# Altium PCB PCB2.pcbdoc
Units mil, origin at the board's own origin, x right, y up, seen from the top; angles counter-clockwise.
Board outline 7800 x 6000 mil, 2 copper layers (Top Layer, Bottom Layer); 55 components, 47 nets, 199 pads, 12 vias.
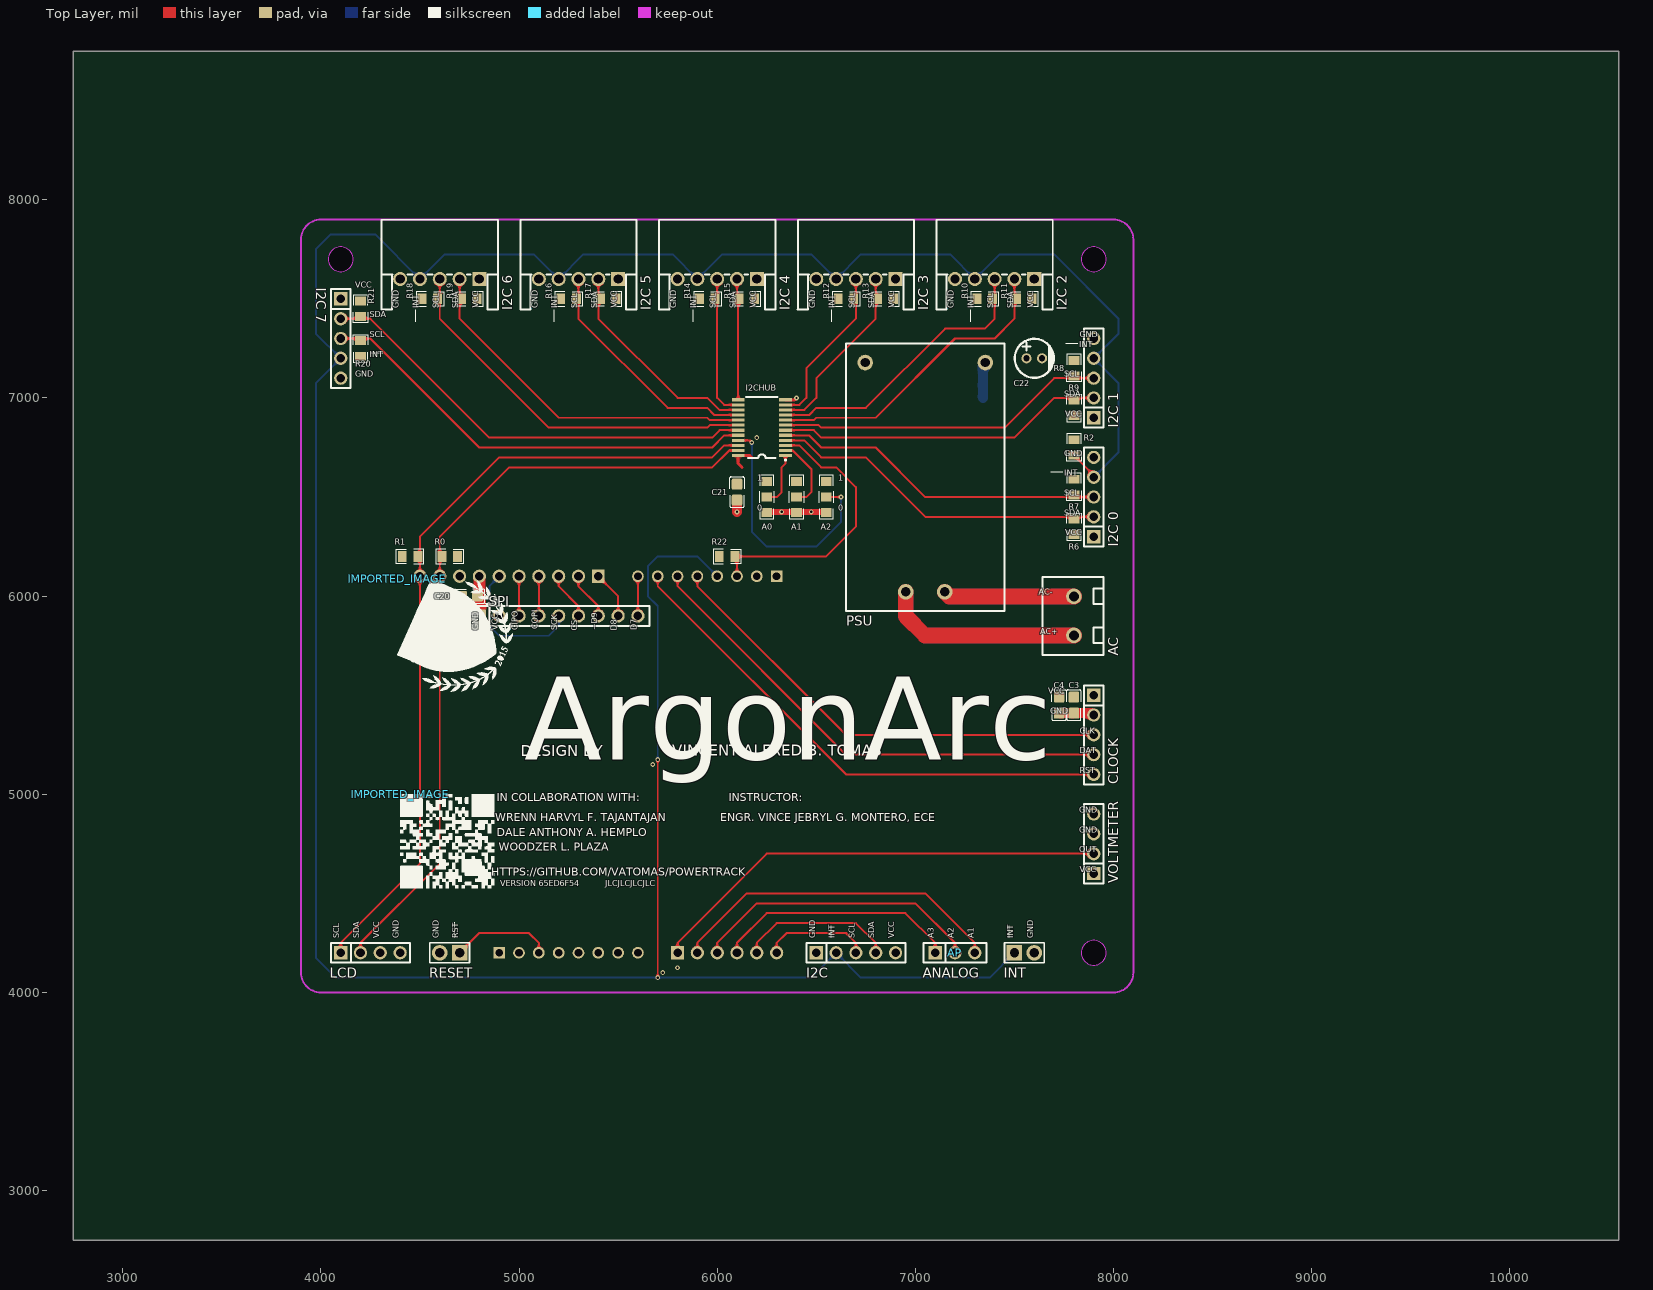
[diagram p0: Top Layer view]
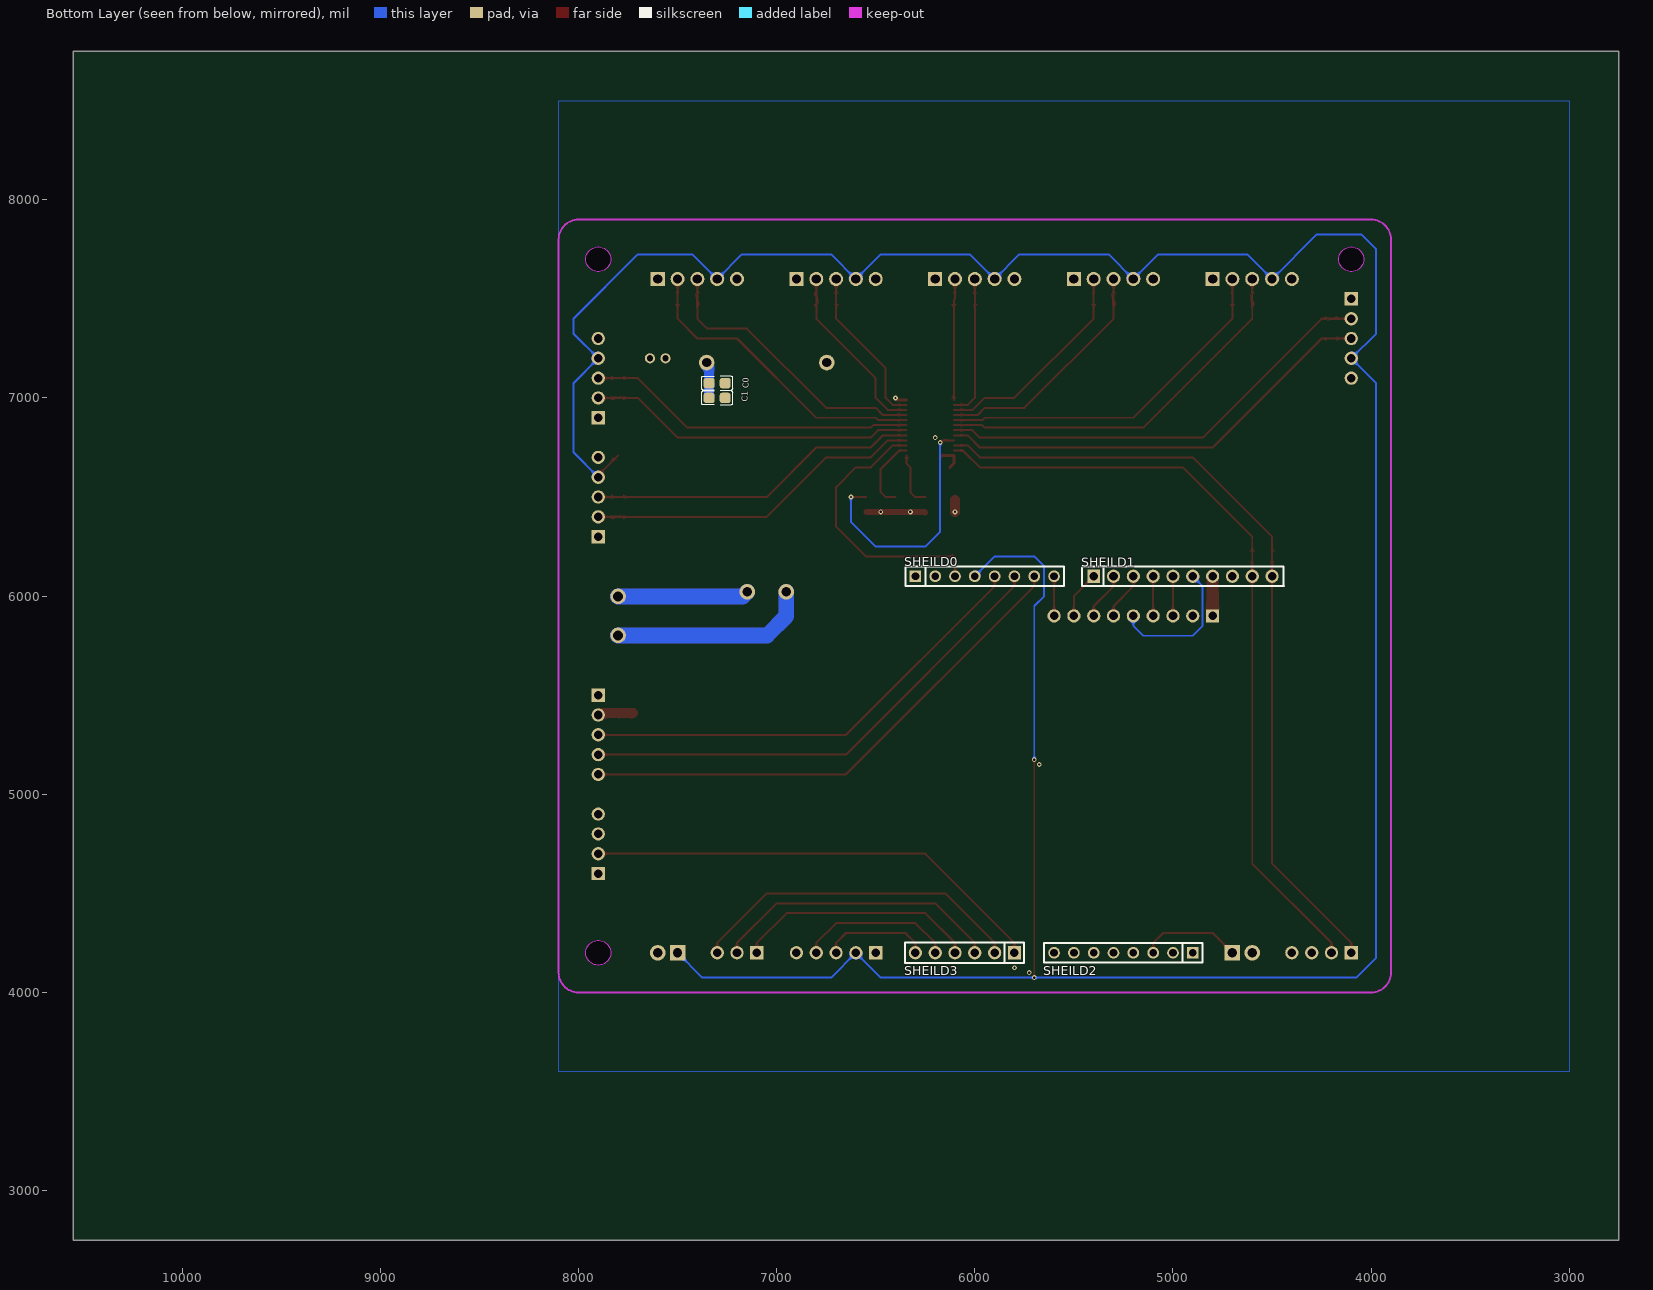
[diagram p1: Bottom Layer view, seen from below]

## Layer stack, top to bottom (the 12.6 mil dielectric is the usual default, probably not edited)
Top Layer: signal copper (thickness not stored)
Dielectric: dielectric 12.6, FR-4, Dk 4.8
Bottom Layer: signal copper (thickness not stored)

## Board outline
10550,2750 2750,2750 2750,8750 10550,8750
cut-out: 7962.99,4200 ccw(c7900,4199.64) 7837.01,4200 ccw(c7900,4200.36)
cut-out: 4162.99,7700 ccw(c4100,7699.64) 4037.01,7700 ccw(c4100,7700.36)
cut-out: 7962.99,7700 ccw(c7900,7699.64) 7837.01,7700 ccw(c7900,7700.36)

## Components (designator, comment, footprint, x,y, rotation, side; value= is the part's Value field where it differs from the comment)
A0 "Solder Switch" "Solder Switch" 6250,6500 r270 top
A1 "Solder Switch" "Solder Switch" 6400,6500 r270 top
A2 "Solder Switch" "Solder Switch" 6550,6500 r270 top
AC "WJ126V-5.0-2P" CONN-TH_WJ126V-5.0-2P 7800,5900 r180 top
AP "PZ254V-11-03P" HDR-TH_3P-P2.54-V-M 7200,4200 r0 top
C0 "CL21B104KBCNNNC" C0805#1 7300,7075 r180 bottom
C1 "CL21B105KBFNNNE" C0805#1 7300,7000 r180 bottom
C3 "CL21B104KBCNNNC" C0805#2 7800,5450 r270 top
C4 "CL21B105KBFNNNE" C0805#2 7725,5450 r270 top
C20 "CL21B104KBCNNNC" C0805#2 4750,6000 r0 top
C21 "CL21B104KBCNNNC" C0805#2 6100,6525 r270 top
C22 "KS476M025D07RR0VH2FP0" CAP-TH_BD5.0-P2.00-D0.8-FD 7600,7200 r0 top
CLOCK "PZ254V-11-05P" HDR-TH_5P-P2.54-V-M 7900,5300 r270 top
I2C "PZ254V-11-05P" HDR-TH_5P-P2.54-V-M 6700,4200 r0 top
"I2C 0" "PZ254V-11-05P" HDR-TH_5P-P2.54-V-M 7900,6500 r90 top
"I2C 1" "PZ254V-11-05P" HDR-TH_5P-P2.54-V-M 7900,7100 r90 top
"I2C 2" "S5B-XH-A-1(LF)(SN)" CONN-TH_S5B-XH-A-1-LF-SN 7400,7600 r0 top
"I2C 3" "S5B-XH-A-1(LF)(SN)" CONN-TH_S5B-XH-A-1-LF-SN 6700,7600 r0 top
"I2C 4" "S5B-XH-A-1(LF)(SN)" CONN-TH_S5B-XH-A-1-LF-SN 6000,7600 r0 top
"I2C 5" "S5B-XH-A-1(LF)(SN)" CONN-TH_S5B-XH-A-1-LF-SN 5300,7600 r0 top
"I2C 6" "S5B-XH-A-1(LF)(SN)" CONN-TH_S5B-XH-A-1-LF-SN 4600,7600 r0 top
"I2C 7" "PZ254V-11-05P" HDR-TH_5P-P2.54-V-M 4100,7300 r270 top
I2CHUB "TCA9548APWR" TSSOP-24_L7.8-W4.4-P0.65-LS6.4-BL 6225,6850 r90 top
IMPORTED_IMAGE "IMPORTED_IMAGE" IMPORTED_IMAGE 4400,5000 r0 top
IMPORTED_IMAGE "IMPORTED_IMAGE" IMPORTED_IMAGE 4385.55,6087.06 r0 top
INT "PZ254V-11-02P" HDR-TH_2P-P2.54-V-M 7550,4200 r0 top
LCD "PZ254V-11-04P" HDR-TH_4P-P2.54-V-M 4250,4200 r0 top
PSU "HLK-PM01" PWRM-TH_HLK-PM01 7050,6600 r90 top
R0 "0805W8F4701T5E" R0805 4650,6200 r180 top
R1 "0805W8F4701T5E" R0805 4450,6200 r0 top
R2 "0805W8F1002T5E" R0805 7800,6750 r90 top
R6 "0805W8F4701T5E" R0805 7800,6350 r270 top
R7 "0805W8F4701T5E" R0805 7800,6550 r90 top
R8 "0805W8F4701T5E" R0805 7800,7150 r90 top
R9 "0805W8F4701T5E" R0805 7800,6950 r270 top
R10 "0805W8F4701T5E" R0805 7350,7500 r180 top
R11 "0805W8F4701T5E" R0805 7550,7500 r0 top
R12 "0805W8F4701T5E" R0805 6650,7500 r180 top
R13 "0805W8F4701T5E" R0805 6850,7500 r0 top
R14 "0805W8F4701T5E" R0805 5950,7500 r180 top
R15 "0805W8F4701T5E" R0805 6150,7500 r0 top
R16 "0805W8F4701T5E" R0805 5250,7500 r180 top
R17 "0805W8F4701T5E" R0805 5450,7500 r0 top
R18 "0805W8F4701T5E" R0805 4550,7500 r180 top
R19 "0805W8F4701T5E" R0805 4750,7500 r0 top
R20 "0805W8F4701T5E" R0805 4200,7250 r270 top
R21 "0805W8F4701T5E" R0805 4200,7450 r90 top
R22 "0805W8F1002T5E" R0805 6050,6200 r180 top
RESET "PZ254V-11-02P" HDR-TH_2P-P2.54-V-M 4650,4200 r180 top
SHEILD0 "PZ254V-11-08P" HDR-TH_8P-P2.54-V-M 5950,6100 r180 bottom
SHEILD1 "X6511WV-10H-C60D30" HDR-TH_10P-P2.54-V-M 4950,6100 r180 bottom
SHEILD2 "PZ254V-11-08P" HDR-TH_8P-P2.54-V-M 5250,4200 r0 bottom
SHEILD3 "PZ254V-11-06P" HDR-TH_6P-P2.54-V-M 6050,4200 r0 bottom
SPI "PZ254-1-09-Z-8.5" HDR-TH_9P-P2.54-V-M 5200,5900 r0 top
VOLTMETER "PZ254V-11-04P" HDR-TH_4P-P2.54-V-M 7900,4750 r90 top

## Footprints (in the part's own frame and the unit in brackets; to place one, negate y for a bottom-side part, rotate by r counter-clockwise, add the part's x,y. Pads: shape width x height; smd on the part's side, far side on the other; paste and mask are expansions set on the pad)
C0805#1 [mm]
  rrect50% 1.41x1.35 smd: 1(-1.03,0) 2(1.03,0)
  silkscreen extent -1.96,-0.9 1.96,0.9
C0805#2 [mm]
  rrect25% 1.41x1.35 smd: 1(-1.03,0) 2(1.03,0)
  silkscreen extent -1.96,-0.9 1.96,0.9
CAP-TH_BD5.0-P2.00-D0.8-FD [mm]
  round 1.3 hole 0.8: 1(-1,0) 2(1,0)
  silkscreen extent -2.5,-2.5 2.5,2.5
CONN-TH_S5B-XH-A-1-LF-SN [mm]
  rect 1.8x1.8 hole 1.2: 1(5.08,0)
  round 1.8 hole 1.2: 2(2.54,0) 3(0,0) 4(-2.54,0) 5(-5.08,0)
  silkscreen extent -7.46,-3.9 7.45,7.6
CONN-TH_WJ126V-5.0-2P [mm]
  round 2 hole 1.3: 1(0,2.501) 2(0,-2.501)
  silkscreen extent -3.8,-5 4,5
HDR-TH_2P-P2.54-V-M [mm]
  rect 2x2 hole 1.2: 1(-1.27,0)
  round 2 hole 1.2: 2(1.27,0)
  silkscreen extent -2.54,-1.27 2.54,1.27
HDR-TH_3P-P2.54-V-M [mm]
  rect 1.7x1.7 hole 1.1: 1(-2.54,0)
  round 1.7 hole 1.1: 2(0,0) 3(2.54,0)
  silkscreen extent -4.02,-1.27 4.02,1.27
HDR-TH_4P-P2.54-V-M [mm]
  rect 1.7x1.7 hole 1.1: 1(-3.81,0)
  round 1.7 hole 1.1: 2(-1.27,0) 3(1.27,0) 4(3.81,0)
  silkscreen extent -5.08,-1.27 5.08,1.27
HDR-TH_5P-P2.54-V-M [mm]
  rect 1.7x1.7 hole 1.1: 1(-5.08,0)
  round 1.7 hole 1.1: 2(-2.54,0) 3(0,0) 4(2.54,0) 5(5.08,0)
  silkscreen extent -6.35,-1.27 6.35,1.27
HDR-TH_6P-P2.54-V-M [mm]
  rect 1.7x1.7 hole 1.1: 1(-6.35,0)
  round 1.7 hole 1.1: 2(-3.81,0) 3(-1.27,0) 4(1.27,0) 5(3.81,0) 6(6.35,0)
  silkscreen extent -7.6,-1.3 7.65,1.3
HDR-TH_8P-P2.54-V-M [mm]
  rect 1.5x1.5 hole 1: 1(-8.89,0)
  round 1.5 hole 1: 2(-6.35,0) 3(-3.81,0) 4(-1.27,0) 5(1.27,0) 6(3.81,0) 7(6.35,0) 8(8.89,0)
  silkscreen extent -10.16,-1.27 10.16,1.27
HDR-TH_9P-P2.54-V-M [mm]
  rect 1.7x1.7 hole 1.1: 1(-10.16,0)
  round 1.7 hole 1.1: 2(-7.62,0) 3(-5.08,0) 4(-2.54,0) 5(0,0) 6(2.54,0) 7(5.08,0) 8(7.62,0) 9(10.16,0)
  silkscreen extent -11.64,-1.27 11.64,1.27
HDR-TH_10P-P2.54-V-M [mm]
  rect 1.575x1.7 hole 1.1: 1(-11.43,0)
  round 1.7 hole 1.1: 2(-8.89,0) 3(-6.35,0) 4(-3.81,0) 5(-1.27,0) 6(1.27,0) 7(3.81,0) 8(6.35,0) 9(8.89,0) 10(11.43,0)
  silkscreen extent -12.9,-1.27 12.95,1.27
IMPORTED_IMAGE [mil]
  silkscreen extent 0,-475 475,0
PWRM-TH_HLK-PM01 [mm]
  round 2 hole 1.2: 1(-14.7,2.5) 2(-14.7,-2.5) 3(14.7,7.7) 4(14.7,-7.7)
  silkscreen extent -17.14,-10.16 17.14,10.16
R0805 [mm]
  rect 1.133x1.377 smd: 1(-1,0) 2(1,0)
  silkscreen extent -1.76,-0.92 1.76,0.92
"Solder Switch" [mm]
  rect 1.133x1.377 smd: 1(-2,0) 2(0,0) 3(2,0)
  silkscreen extent -2.76,-0.92 2.76,0.92
TSSOP-24_L7.8-W4.4-P0.65-LS6.4-BL [mm]
  rect 0.4x1.65 smd: 1(-3.575,-3.023) 2(-2.925,-3.023) 3(-2.275,-3.023) 4(-1.625,-3.023) 5(-0.975,-3.023) 6(-0.325,-3.023) 7(0.325,-3.023) 8(0.975,-3.023) 9(1.625,-3.023) 10(2.275,-3.023) 11(2.925,-3.023) 12(3.575,-3.023) 13(3.575,3.023) 14(2.925,3.023) 15(2.275,3.023) 16(1.625,3.023) 17(0.975,3.023) 18(0.325,3.023) 19(-0.325,3.023) 20(-0.975,3.023) 21(-1.625,3.023) 22(-2.275,3.023) 23(-2.925,3.023) 24(-3.575,3.023)
  silkscreen extent -4.24,-3.15 3.94,2.01

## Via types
v1: diameter 24, hole 12, Top Layer to Bottom Layer, 12 vias

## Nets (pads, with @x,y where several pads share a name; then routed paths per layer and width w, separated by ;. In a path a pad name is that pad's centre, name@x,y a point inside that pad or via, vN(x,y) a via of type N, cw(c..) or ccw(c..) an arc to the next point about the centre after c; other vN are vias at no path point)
$1N166390: SHEILD1.2 SPI.7 | length 241.4
  Top Layer w10: SHEILD1.2 5300,6050 5400,5950 SPI.7
$1N166393: SHEILD1.1 SPI.8 | length 241.4
  Top Layer w10: SHEILD1.1 5500,6000 SPI.8
$1N166401: SHEILD0.8 SPI.9 | length 200
  Top Layer w10: SPI.9 SHEILD0.8
$1N175997: I2C.4 SHEILD3.5 | length 782.8
  Top Layer w10: SHEILD3.5 6200,4250 6300,4350 6700,4350 6800,4250 I2C.4
$1N176000: I2C.3 SHEILD3.6 | length 541.4
  Top Layer w10: SHEILD3.6 6300,4250 6350,4300 6650,4300 6700,4250 I2C.3
$1N176012: AP.1 SHEILD3.4 | length 1224.3
  Top Layer w10: SHEILD3.4 6100,4250 6250,4400 6950,4400 7100,4250 AP.1
$1N176017: AP.2 SHEILD3.3 | length 1465.7
  Top Layer w10: SHEILD3.3 6000,4250 6200,4450 7000,4450 7200,4250 AP.2
$1N176022: AP.3 SHEILD3.2 | length 1707.1
  Top Layer w10: SHEILD3.2 5900,4250 6150,4500 7050,4500 7300,4250 AP.3
+5V: "I2C 0.1" "I2C 1.1" "I2C 2.1" "I2C 3.1" "I2C 4.1" "I2C 5.1" "I2C 6.1" "I2C 7.1" A0.1 A1.1 A2.1 C0.1 C1.1 C3.1 C4.1 C20.1 C21.1 C22.1 CLOCK.1 I2C.5 I2CHUB.24 LCD.3 PSU.4 R0.1 R1.1 R2.2 R6.2 R7.2 R8.2 R9.2 R10.2 R11.2 R12.2 R13.2 R14.2 R15.2 R16.2 R17.2 R18.2 R19.2 R20.2 R21.2 R22.2 SHEILD1.8 SHEILD2.2 SHEILD2.5 SHEILD2.8 SPI.2 VOLTMETER.1 | length 323.9
  Top Layer w15: 6125,6650 6106,6669 I2CHUB.24 6165.74,6709.26 6175,6700
  Bottom Layer w50: C1.1 C0.1 7340.55,7166.14 PSU.4
A0: A0.2 I2CHUB.1 | length 277.5
  Top Layer w10: A0.2 6300,6500 6325,6525 6325,6650 6344,6669 I2CHUB.1
A1: A1.2 I2CHUB.2 | length 371.4
  Top Layer w10: I2CHUB.2 6381.48,6734.85 6475,6641.33 6475,6525 6450,6500 A1.2
A2: A2.2 I2CHUB.21 | length 1256.4
  Top Layer w10: I2CHUB.21 6163.97,6786.03 v1(6175,6775) ; A2.2 v1(6625,6500)
  Bottom Layer w10: v1(6175,6775) 6175,6325 6250,6250 6500,6250 6625,6375 v1(6625,6500)
AC+: AC.1 PSU.1 | length 2022.8
  Top Layer w80: PSU.1 6951.57,5898.43 7048.45,5801.55 AC.1
  Bottom Layer w80: PSU.1 6951.57,5898.43 7048.45,5801.55 AC.1
AC-: AC.2 PSU.2 | length 1322.1
  Top Layer w80: PSU.2 7171.23,5998.45 AC.2
  Bottom Layer w80: PSU.2 7171.23,5998.45 AC.2
CIPO: SHEILD1.5 SPI.3 | length 200
  Top Layer w10: SPI.3 SHEILD1.5
COPI: SHEILD1.4 SPI.4 | length 200
  Top Layer w10: SPI.4 SHEILD1.4
CS: SHEILD1.3 SPI.6 | length 241.4
  Top Layer w10: SHEILD1.3 5200,6050 5300,5950 SPI.6
D0: SHEILD0.1
D1: SHEILD0.2
GND: "I2C 0.5" "I2C 1.5" "I2C 2.5" "I2C 3.5" "I2C 4.5" "I2C 5.5" "I2C 6.5" "I2C 7.5" A0.3 A1.3 A2.3 C0.2 C1.2 C3.2 C4.2 C20.2 C21.2 C22.2 CLOCK.2 I2C.1 I2CHUB.12 INT.2 LCD.4 PSU.3 RESET.2 SHEILD1.7 SHEILD2.1 SHEILD2.6 SHEILD2.7 SPI.1 VOLTMETER.3 VOLTMETER.4 | length 801.3
  Top Layer w10: A2.3@6546.26,6425 A2.3
  Top Layer w15: I2CHUB.12 6390.74,6990.74 v1(6400,7000)
  Top Layer w30: A0.3 6253.74,6425 v1(6325,6425) v1(6475,6425) A2.3@6546.26,6425
  Top Layer w50: v1(6100,6425) C21.2 ; C4.2 C3.2 7890.55,5409.45 CLOCK.2
  Top Layer w60: SPI.1 SHEILD1.7
  other v1: 5725,4100 5800,4125 5675,5150 6200,6800
I2C~RESET: I2CHUB.3 R22.1 SHEILD0.3 | length 1405.3
  Top Layer w10: SHEILD0.3 6100,6200 6550,6200 6700,6350 6700,6550 6600,6650 6525,6650 6414.56,6760.44 I2CHUB.3
RTC_CLK: CLOCK.3 SHEILD0.5 | length 2360.7
  Top Layer w10: SHEILD0.5 5900,6050 6650,5300 CLOCK.3
RTC_DAT: CLOCK.4 SHEILD0.6 | length 2502.1
  Top Layer w10: SHEILD0.6 5800,6050 6650,5200 CLOCK.4
RTC_RST: CLOCK.5 SHEILD0.7 | length 2643.5
  Top Layer w10: SHEILD0.7 5700,6050 6650,5100 CLOCK.5
SC0: "I2C 0.3" I2CHUB.5 R7.1 | length 1685.1
  Top Layer w10: I2CHUB.5 6463.38,6811.62 6525,6750 6800,6750 7050,6500 7900,6500
SC1: "I2C 1.3" I2CHUB.7 R8.1 | length 1664.9
  Top Layer w10: I2CHUB.7 6512.21,6862.79 6525,6850 7450,6850 7700,7100 7900,7100
SC2: "I2C 2.3" I2CHUB.9 R10.1 | length 1457.3
  Top Layer w10: I2CHUB.9 6463.98,6913.98 6500,6950 6750,6950 7150,7350 7350,7350 7400,7400 7400,7600
SC3: "I2C 3.3" I2CHUB.11 R12.1 | length 824
  Top Layer w10: I2CHUB.11 6415.16,6965.16 6450,7000 6450,7150 6700,7400 6700,7600
SC4: "I2C 4.3" I2CHUB.14 R14.1 | length 720.4
  Top Layer w10: 6000,7600 6000,7000 6034.84,6965.16 I2CHUB.14
SC5: "I2C 5.3" I2CHUB.16 R16.1 | length 1207.3
  Top Layer w10: 5300,7600 5300,7400 5750,6950 5950,6950 5986.02,6913.98 I2CHUB.16
SC6: "I2C 6.3" I2CHUB.18 R18.1 | length 1939.1
  Top Layer w10: 4600,7600 4600,7400 5150,6850 5950,6850 5962.79,6862.79 I2CHUB.18
SC7: "I2C 7.3" I2CHUB.20 R20.1 | length 2259.3
  Top Layer w10: 4100,7300 4250,7300 4800,6750 5975,6750 6036.62,6811.62 I2CHUB.20
SCK: SHEILD1.6 SPI.5 | length 712.1
  Bottom Layer w10: SHEILD1.6 4850,6050 4850,5850 4900,5800 5150,5800 5200,5850 SPI.5
SCL: I2CHUB.22 LCD.1 R1.2 SHEILD1.10 | length 4062.4
  Top Layer w10: LCD.1 4100,4250 4500,4650 SHEILD1.10 4500,6300 4900,6700 5975,6700 6035.44,6760.44 I2CHUB.22
SD0: "I2C 0.2" I2CHUB.4 R6.1 | length 1715.9
  Top Layer w10: I2CHUB.4 6438.97,6786.03 6525,6700 6750,6700 7050,6400 7900,6400
SD1: "I2C 1.2" I2CHUB.6 R9.1 | length 1654.3
  Top Layer w10: I2CHUB.6 6487.79,6837.21 6525,6800 7500,6800 7700,7000 7900,7000
SD2: "I2C 2.2" I2CHUB.8 R11.1 | length 1567.9
  Top Layer w10: I2CHUB.8 6488.39,6888.39 6500,6900 6800,6900 7200,7300 7400,7300 7500,7400 7500,7600
SD3: "I2C 3.2" I2CHUB.10 R13.1 | length 905.3
  Top Layer w10: I2CHUB.10 6439.57,6939.57 6500,7000 6500,7100 6800,7400 6800,7600
SD4: "I2C 4.2" I2CHUB.13 R15.1 | length 611.7
  Top Layer w10: 6100,7600 6100,7500 6106,7494 I2CHUB.13
SD5: "I2C 5.2" I2CHUB.15 R17.1 | length 1096.7
  Top Layer w10: 5400,7600 5400,7400 5800,7000 5950,7000 6010.43,6939.57 I2CHUB.15
SD6: "I2C 6.2" I2CHUB.17 R19.1 | length 1817.9
  Top Layer w10: 4700,7600 4700,7400 5200,6900 5950,6900 5961.61,6888.39 I2CHUB.17
SD7: "I2C 7.2" I2CHUB.19 R21.1 | length 2269.9
  Top Layer w10: 4100,7400 4250,7400 4850,6800 5975,6800 6012.21,6837.21 I2CHUB.19
SDA: I2CHUB.23 LCD.2 R0.2 SHEILD1.9 | length 3951.8
  Top Layer w10: LCD.2 4200,4250 4600,4650 SHEILD1.9 4600,6300 4950,6650 5975,6650 6059.85,6734.85 I2CHUB.23
VLTMR: SHEILD3.1 VOLTMETER.2 | length 2336.4
  Top Layer w10: SHEILD3.1 5800,4250 6250,4700 VOLTMETER.2
~INT: "I2C 0.4" "I2C 1.4" "I2C 2.4" "I2C 3.4" "I2C 4.4" "I2C 5.4" "I2C 6.4" "I2C 7.4" I2C.2 INT.1 R2.1 SHEILD0.4 | length 15790.4
  Top Layer w10: v1(5700,4075) v1(5700,5175) ; R2.1 7900,6610.63 7900,6600
  Bottom Layer w10: v1(5700,5175) 5700,5950 5650,6000 5650,6150 5700,6200 5900,6200 SHEILD0.4 ; INT.1 7375,4075 6725,4075 I2C.2 6475,4075 v1(5700,4075) 4075,4075 3975,4175 3975,7075 4100,7200 3975,7325 3975,7750 4050,7825 4275,7825 4500,7600 4625,7725 5075,7725 5200,7600 5325,7725 5775,7725 5900,7600 6025,7725 6475,7725 6600,7600 6725,7725 7175,7725 7300,7600 7425,7725 7700,7725 8025,7400 8025,7325 7900,7200 8025,7075 8025,6725 7900,6600
~RESET: RESET.1 SHEILD2.3 | length 512.1
  Top Layer w10: RESET.1 4800,4300 5050,4300 5100,4250 SHEILD2.3
"": SHEILD2.4

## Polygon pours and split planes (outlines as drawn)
+5V on Top Layer (solid, remove dead copper, pour order 0): 3600,3000 8700,3000 8700,7900 3600,7900
GND on Bottom Layer (solid, remove dead copper, pour order 1): 3000,3600 8100,3600 8100,8500 3000,8500

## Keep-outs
Board Outline Layer:
  lines w10 net "": 3900,4100 ccw(c4000,4100) 4000,4000 8000,4000 ccw(c8000,4100) 8100,4100 8100,7800 ccw(c8000,7800) 8000,7900 4000,7900 ccw(c4000,7800) 3900,7800 3900,4100
Multi-Layer:
  region net "": 7962.99,4200 ccw(c7900,4199.64) 7837.01,4200 ccw(c7900,4200.36)
  region net "": 4162.99,7700 ccw(c4100,7699.64) 4037.01,7700 ccw(c4100,7700.36)
  region net "": 7962.99,7700 ccw(c7900,7699.64) 7837.01,7700 ccw(c7900,7700.36)

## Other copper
Top Layer:
  drawing of 163 lines, arcs and shapes, not listed
Bottom Layer:
  region net ~INT: 5975.11,6131.96 5968.04,6124.89 5969.22,6123.63 5969.89,6122.82 5970.48,6122.03 5970.99,6121.26 5971.42,6120.5 5971.77,6119.76 5972.06,6119.03 5972.29,6118.3 5972.45,6117.59 5972.56,6116.88 5972.63,6116.17 5972.64,6115.46 5972.62,6114.74 5972.52,6113.66 5972.29,6112.19 5971.26,6107.38 5970.85,6105.11 5970.61,6103.15 5970.48,6101.04 5970.48,6099.34 5970.53,6098.15 6001.85,6129.47 6000.08,6129.53 5998.42,6129.5 5996.34,6129.34 5994.42,6129.07 5990.93,6128.38 5987.43,6127.64 5986.34,6127.48 5985.26,6127.38 5984.54,6127.36 5983.83,6127.37 5983.12,6127.44 5982.41,6127.55 5981.7,6127.71 5980.97,6127.94 5980.24,6128.23 5979.5,6128.58 5978.74,6129.01 5977.97,6129.52 5977.18,6130.11 5976.37,6130.78
  region net SCK: 4864.25,6071.32 4871.32,6064.25 4872.79,6065.63 4873.74,6066.41 4874.66,6067.09 4875.55,6067.67 4876.42,6068.16 4877.27,6068.56 4878.11,6068.88 4878.94,6069.13 4879.76,6069.3 4880.57,6069.41 4881.38,6069.46 4882.18,6069.45 4882.99,6069.4 4884.22,6069.25 4885.89,6068.92 4891.38,6067.57 4893.99,6067.04 4896.26,6066.73 4898.09,6066.58 4900.03,6066.53 4902.1,6066.6 4866.6,6102.1 4866.53,6100.03 4866.58,6098.09 4866.73,6096.26 4867.04,6093.99 4867.57,6091.38 4868.92,6085.89 4869.25,6084.22 4869.4,6082.99 4869.45,6082.18 4869.46,6081.38 4869.41,6080.57 4869.3,6079.76 4869.13,6078.94 4868.88,6078.11 4868.56,6077.27 4868.16,6076.42 4867.67,6075.55 4867.09,6074.66 4866.41,6073.74 4865.63,6072.79
  region net +5V: 7315.55,7125.14 7365.55,7125.14 7365.61,7126.91 7365.77,7128.58 7366.03,7130.16 7366.4,7131.66 7366.85,7133.08 7367.39,7134.44 7368.01,7135.74 7368.71,7136.99 7369.48,7138.2 7370.6,7139.75 7372.15,7141.64 7374.91,7144.61 7381.87,7151.8 7382.68,7152.7 7323.62,7152.7 7324.13,7152.04 7324.53,7151.36 7324.83,7150.65 7325.02,7149.92 7325.12,7149.16 7325.13,7148.39 7325.06,7147.59 7324.92,7146.78 7324.71,7145.95 7324.44,7145.11 7323.74,7143.37 7322.86,7141.6 7319.17,7135.15 7317.66,7132.35 7316.82,7130.5 7316.15,7128.68 7315.89,7127.78 7315.71,7126.89 7315.59,7126.01
  region net +5V: 7315.55,7000 7365.55,7000 ccw(c7247.11,7000) 7355.2,7048.43 7325.9,7048.43 ccw(c7433.99,7000)
  region net +5V: 7365.55,7166.14 7315.55,7166.14 ccw(c7853.62,7166.14) 7319.44,7101.57 7361.66,7101.57 ccw(c6827.48,7166.14)
  region net +5V: 7365.55,7075 7315.55,7075 ccw(c7619.08,7075) 7319.44,7026.57 7361.66,7026.57 ccw(c7062.02,7075)
  region net ~INT: 7269.42,7637.65 7262.35,7630.58 7263.84,7628.99 7264.67,7627.98 7265.4,7627 7266.02,7626.05 7266.54,7625.12 7266.96,7624.21 7267.3,7623.32 7267.55,7622.44 7267.73,7621.57 7267.83,7620.71 7267.88,7619.85 7267.86,7618.99 7267.79,7618.14 7267.61,7616.84 7267.24,7615.06 7265.85,7609.76 7265.24,7607.03 7264.86,7604.65 7264.66,7602.74 7264.57,7600.7 7264.6,7598.54 7264.64,7597.78 7302.22,7635.36 7300,7635.44 7297.92,7635.38 7295.97,7635.22 7293.55,7634.87 7290.77,7634.28 7285.39,7632.88 7283.6,7632.47 7282.3,7632.26 7281.43,7632.17 7280.58,7632.13 7279.72,7632.14 7278.86,7632.21 7278,7632.35 7277.13,7632.57 7276.24,7632.86 7275.34,7633.24 7274.42,7633.71 7273.48,7634.28 7272.51,7634.95 7271.51,7635.73 7269.96,7637.12
  region net ~INT: 7337.65,7630.58 7330.58,7637.65 7328.99,7636.16 7327.98,7635.33 7327,7634.6 7326.05,7633.98 7325.12,7633.46 7324.21,7633.04 7323.32,7632.7 7322.44,7632.45 7321.57,7632.27 7320.71,7632.17 7319.85,7632.12 7318.99,7632.14 7318.14,7632.21 7316.84,7632.39 7315.06,7632.76 7309.76,7634.15 7307.03,7634.76 7304.65,7635.14 7302.74,7635.34 7300.7,7635.43 7298.54,7635.4 7297.78,7635.36 7335.36,7597.78 7335.44,7600 7335.38,7602.08 7335.22,7604.03 7334.87,7606.45 7334.28,7609.23 7332.88,7614.61 7332.47,7616.4 7332.26,7617.7 7332.17,7618.57 7332.13,7619.42 7332.14,7620.28 7332.21,7621.14 7332.35,7622 7332.57,7622.87 7332.86,7623.76 7333.24,7624.66 7333.71,7625.58 7334.28,7626.52 7334.95,7627.49 7335.73,7628.49 7337.12,7630.04
  region net ~INT: 6637.65,7630.58 6630.58,7637.65 6628.99,7636.16 6627.98,7635.33 6627,7634.6 6626.05,7633.98 6625.12,7633.46 6624.21,7633.04 6623.32,7632.7 6622.44,7632.45 6621.57,7632.27 6620.71,7632.17 6619.85,7632.12 6618.99,7632.14 6618.14,7632.21 6616.84,7632.39 6615.06,7632.76 6609.76,7634.15 6607.03,7634.76 6604.65,7635.14 6602.74,7635.34 6600.7,7635.43 6598.54,7635.4 6597.78,7635.36 6635.36,7597.78 6635.44,7600 6635.38,7602.08 6635.22,7604.03 6634.87,7606.45 6634.28,7609.23 6632.88,7614.61 6632.47,7616.4 6632.26,7617.7 6632.17,7618.57 6632.13,7619.42 6632.14,7620.28 6632.21,7621.14 6632.35,7622 6632.57,7622.87 6632.86,7623.76 6633.24,7624.66 6633.71,7625.58 6634.28,7626.52 6634.95,7627.49 6635.73,7628.49 6637.12,7630.04
  region net ~INT: 6569.42,7637.65 6562.35,7630.58 6563.84,7628.99 6564.67,7627.98 6565.4,7627 6566.02,7626.05 6566.54,7625.12 6566.96,7624.21 6567.3,7623.32 6567.55,7622.44 6567.73,7621.57 6567.83,7620.71 6567.88,7619.85 6567.86,7618.99 6567.79,7618.14 6567.61,7616.84 6567.24,7615.06 6565.85,7609.76 6565.24,7607.03 6564.86,7604.65 6564.66,7602.74 6564.57,7600.7 6564.6,7598.54 6564.64,7597.78 6602.22,7635.36 6600,7635.44 6597.92,7635.38 6595.97,7635.22 6593.55,7634.87 6590.77,7634.28 6585.39,7632.88 6583.6,7632.47 6582.3,7632.26 6581.43,7632.17 6580.58,7632.13 6579.72,7632.14 6578.86,7632.21 6578,7632.35 6577.13,7632.57 6576.24,7632.86 6575.34,7633.24 6574.42,7633.71 6573.48,7634.28 6572.51,7634.95 6571.51,7635.73 6569.96,7637.12
  region net ~INT: 6564.25,4171.32 6571.32,4164.25 6572.79,4165.63 6573.74,4166.41 6574.66,4167.09 6575.55,4167.67 6576.42,4168.16 6577.27,4168.56 6578.11,4168.88 6578.94,4169.13 6579.76,4169.3 6580.57,4169.41 6581.38,4169.46 6582.18,4169.45 6582.99,4169.4 6584.22,4169.25 6585.89,4168.92 6591.38,4167.57 6593.99,4167.04 6596.26,4166.73 6598.09,4166.58 6600.03,4166.53 6602.1,4166.6 6566.6,4202.1 6566.53,4200.03 6566.58,4198.09 6566.73,4196.26 6567.04,4193.99 6567.57,4191.38 6568.92,4185.89 6569.25,4184.22 6569.4,4182.99 6569.45,4182.18 6569.46,4181.38 6569.41,4180.57 6569.3,4179.76 6569.13,4178.94 6568.88,4178.11 6568.56,4177.27 6568.16,4176.42 6567.67,4175.55 6567.09,4174.66 6566.41,4173.74 6565.63,4172.79
  region net ~INT: 6628.68,4164.25 6635.75,4171.32 6634.37,4172.79 6633.59,4173.74 6632.91,4174.66 6632.33,4175.55 6631.84,4176.42 6631.44,4177.27 6631.12,4178.11 6630.87,4178.94 6630.7,4179.76 6630.59,4180.57 6630.54,4181.38 6630.55,4182.18 6630.6,4182.99 6630.75,4184.22 6631.08,4185.89 6632.43,4191.38 6632.96,4193.99 6633.27,4196.26 6633.42,4198.09 6633.47,4200.03 6633.4,4202.1 6597.9,4166.6 6599.97,4166.53 6601.91,4166.58 6603.74,4166.73 6606.01,4167.04 6608.62,4167.57 6614.11,4168.92 6615.78,4169.25 6617.01,4169.4 6617.82,4169.45 6618.62,4169.46 6619.43,4169.41 6620.24,4169.3 6621.06,4169.13 6621.89,4168.88 6622.73,4168.56 6623.58,4168.16 6624.45,4167.67 6625.34,4167.09 6626.26,4166.41 6627.21,4165.63
  region net ~INT: 7450.02,4157.09 7457.09,4150.02 cw(c7483.61,4123.51) 7478.31,4160.63 7460.63,4178.31 cw(c7423.51,4183.61)
  region net ~INT: 7935.75,6628.68 7928.68,6635.75 7927.21,6634.37 7926.26,6633.59 7925.34,6632.91 7924.45,6632.33 7923.58,6631.84 7922.73,6631.44 7921.89,6631.12 7921.06,6630.87 7920.24,6630.7 7919.43,6630.59 7918.62,6630.54 7917.82,6630.55 7917.01,6630.6 7915.78,6630.75 7914.11,6631.08 7908.62,6632.43 7906.01,6632.96 7903.74,6633.27 7901.91,6633.42 7899.97,6633.47 7897.9,6633.4 7933.4,6597.9 7933.47,6599.97 7933.42,6601.91 7933.27,6603.74 7932.96,6606.01 7932.43,6608.62 7931.08,6614.11 7930.75,6615.78 7930.6,6617.01 7930.55,6617.82 7930.54,6618.62 7930.59,6619.43 7930.7,6620.24 7930.87,6621.06 7931.12,6621.89 7931.44,6622.73 7931.84,6623.58 7932.33,6624.45 7932.91,6625.34 7933.59,6626.26 7934.37,6627.21
  region net ~INT: 7928.68,7164.25 7935.75,7171.32 7934.37,7172.79 7933.59,7173.74 7932.91,7174.66 7932.33,7175.55 7931.84,7176.42 7931.44,7177.27 7931.12,7178.11 7930.87,7178.94 7930.7,7179.76 7930.59,7180.57 7930.54,7181.38 7930.55,7182.18 7930.6,7182.99 7930.75,7184.22 7931.08,7185.89 7932.43,7191.38 7932.96,7193.99 7933.27,7196.26 7933.42,7198.09 7933.47,7200.03 7933.4,7202.1 7897.9,7166.6 7899.97,7166.53 7901.91,7166.58 7903.74,7166.73 7906.01,7167.04 7908.62,7167.57 7914.11,7168.92 7915.78,7169.25 7917.01,7169.4 7917.82,7169.45 7918.62,7169.46 7919.43,7169.41 7920.24,7169.3 7921.06,7169.13 7921.89,7168.88 7922.73,7168.56 7923.58,7168.16 7924.45,7167.67 7925.34,7167.09 7926.26,7166.41 7927.21,7165.63
  region net ~INT: 7935.75,7228.68 7928.68,7235.75 7927.21,7234.37 7926.26,7233.59 7925.34,7232.91 7924.45,7232.33 7923.58,7231.84 7922.73,7231.44 7921.89,7231.12 7921.06,7230.87 7920.24,7230.7 7919.43,7230.59 7918.62,7230.54 7917.82,7230.55 7917.01,7230.6 7915.78,7230.75 7914.11,7231.08 7908.62,7232.43 7906.01,7232.96 7903.74,7233.27 7901.91,7233.42 7899.97,7233.47 7897.9,7233.4 7933.4,7197.9 7933.47,7199.97 7933.42,7201.91 7933.27,7203.74 7932.96,7206.01 7932.43,7208.62 7931.08,7214.11 7930.75,7215.78 7930.6,7217.01 7930.55,7217.82 7930.54,7218.62 7930.59,7219.43 7930.7,7220.24 7930.87,7221.06 7931.12,7221.89 7931.44,7222.73 7931.84,7223.58 7932.33,7224.45 7932.91,7225.34 7933.59,7226.26 7934.37,7227.21
  region net ~INT: 5237.65,7630.58 5230.58,7637.65 5228.99,7636.16 5227.98,7635.33 5227,7634.6 5226.05,7633.98 5225.12,7633.46 5224.21,7633.04 5223.32,7632.7 5222.44,7632.45 5221.57,7632.27 5220.71,7632.17 5219.85,7632.12 5218.99,7632.14 5218.14,7632.21 5216.84,7632.39 5215.06,7632.76 5209.76,7634.15 5207.03,7634.76 5204.65,7635.14 5202.74,7635.34 5200.7,7635.43 5198.54,7635.4 5197.78,7635.36 5235.36,7597.78 5235.44,7600 5235.38,7602.08 5235.22,7604.03 5234.87,7606.45 5234.28,7609.23 5232.88,7614.61 5232.47,7616.4 5232.26,7617.7 5232.17,7618.57 5232.13,7619.42 5232.14,7620.28 5232.21,7621.14 5232.35,7622 5232.57,7622.87 5232.86,7623.76 5233.24,7624.66 5233.71,7625.58 5234.28,7626.52 5234.95,7627.49 5235.73,7628.49 5237.12,7630.04
  region net ~INT: 5169.42,7637.65 5162.35,7630.58 5163.84,7628.99 5164.67,7627.98 5165.4,7627 5166.02,7626.05 5166.54,7625.12 5166.96,7624.21 5167.3,7623.32 5167.55,7622.44 5167.73,7621.57 5167.83,7620.71 5167.88,7619.85 5167.86,7618.99 5167.79,7618.14 5167.61,7616.84 5167.24,7615.06 5165.85,7609.76 5165.24,7607.03 5164.86,7604.65 5164.66,7602.74 5164.57,7600.7 5164.6,7598.54 5164.64,7597.78 5202.22,7635.36 5200,7635.44 5197.92,7635.38 5195.97,7635.22 5193.55,7634.87 5190.77,7634.28 5185.39,7632.88 5183.6,7632.47 5182.3,7632.26 5181.43,7632.17 5180.58,7632.13 5179.72,7632.14 5178.86,7632.21 5178,7632.35 5177.13,7632.57 5176.24,7632.86 5175.34,7633.24 5174.42,7633.71 5173.48,7634.28 5172.51,7634.95 5171.51,7635.73 5169.96,7637.12
  region net ~INT: 4469.42,7637.65 4462.35,7630.58 4463.84,7628.99 4464.67,7627.98 4465.4,7627 4466.02,7626.05 4466.54,7625.12 4466.96,7624.21 4467.3,7623.32 4467.55,7622.44 4467.73,7621.57 4467.83,7620.71 4467.88,7619.85 4467.86,7618.99 4467.79,7618.14 4467.61,7616.84 4467.24,7615.06 4465.85,7609.76 4465.24,7607.03 4464.86,7604.65 4464.66,7602.74 4464.57,7600.7 4464.6,7598.54 4464.64,7597.78 4502.22,7635.36 4500,7635.44 4497.92,7635.38 4495.97,7635.22 4493.55,7634.87 4490.77,7634.28 4485.39,7632.88 4483.6,7632.47 4482.3,7632.26 4481.43,7632.17 4480.58,7632.13 4479.72,7632.14 4478.86,7632.21 4478,7632.35 4477.13,7632.57 4476.24,7632.86 4475.34,7633.24 4474.42,7633.71 4473.48,7634.28 4472.51,7634.95 4471.51,7635.73 4469.96,7637.12
  region net ~INT: 4537.65,7630.58 4530.58,7637.65 4528.99,7636.16 4527.98,7635.33 4527,7634.6 4526.05,7633.98 4525.12,7633.46 4524.21,7633.04 4523.32,7632.7 4522.44,7632.45 4521.57,7632.27 4520.71,7632.17 4519.85,7632.12 4518.99,7632.14 4518.14,7632.21 4516.84,7632.39 4515.06,7632.76 4509.76,7634.15 4507.03,7634.76 4504.65,7635.14 4502.74,7635.34 4500.7,7635.43 4498.54,7635.4 4497.78,7635.36 4535.36,7597.78 4535.44,7600 4535.38,7602.08 4535.22,7604.03 4534.87,7606.45 4534.28,7609.23 4532.88,7614.61 4532.47,7616.4 4532.26,7617.7 4532.17,7618.57 4532.13,7619.42 4532.14,7620.28 4532.21,7621.14 4532.35,7622 4532.57,7622.87 4532.86,7623.76 4533.24,7624.66 4533.71,7625.58 4534.28,7626.52 4534.95,7627.49 4535.73,7628.49 4537.12,7630.04
  region net ~INT: 5937.65,7630.58 5930.58,7637.65 5928.99,7636.16 5927.98,7635.33 5927,7634.6 5926.05,7633.98 5925.12,7633.46 5924.21,7633.04 5923.32,7632.7 5922.44,7632.45 5921.57,7632.27 5920.71,7632.17 5919.85,7632.12 5918.99,7632.14 5918.14,7632.21 5916.84,7632.39 5915.06,7632.76 5909.76,7634.15 5907.03,7634.76 5904.65,7635.14 5902.74,7635.34 5900.7,7635.43 5898.54,7635.4 5897.78,7635.36 5935.36,7597.78 5935.44,7600 5935.38,7602.08 5935.22,7604.03 5934.87,7606.45 5934.28,7609.23 5932.88,7614.61 5932.47,7616.4 5932.26,7617.7 5932.17,7618.57 5932.13,7619.42 5932.14,7620.28 5932.21,7621.14 5932.35,7622 5932.57,7622.87 5932.86,7623.76 5933.24,7624.66 5933.71,7625.58 5934.28,7626.52 5934.95,7627.49 5935.73,7628.49 5937.12,7630.04
  region net ~INT: 5869.42,7637.65 5862.35,7630.58 5863.84,7628.99 5864.67,7627.98 5865.4,7627 5866.02,7626.05 5866.54,7625.12 5866.96,7624.21 5867.3,7623.32 5867.55,7622.44 5867.73,7621.57 5867.83,7620.71 5867.88,7619.85 5867.86,7618.99 5867.79,7618.14 5867.61,7616.84 5867.24,7615.06 5865.85,7609.76 5865.24,7607.03 5864.86,7604.65 5864.66,7602.74 5864.57,7600.7 5864.6,7598.54 5864.64,7597.78 5902.22,7635.36 5900,7635.44 5897.92,7635.38 5895.97,7635.22 5893.55,7634.87 5890.77,7634.28 5885.39,7632.88 5883.6,7632.47 5882.3,7632.26 5881.43,7632.17 5880.58,7632.13 5879.72,7632.14 5878.86,7632.21 5878,7632.35 5877.13,7632.57 5876.24,7632.86 5875.34,7633.24 5874.42,7633.71 5873.48,7634.28 5872.51,7634.95 5871.51,7635.73 5869.96,7637.12
  region net ~INT: 4064.25,7171.32 4071.32,7164.25 4072.79,7165.63 4073.74,7166.41 4074.66,7167.09 4075.55,7167.67 4076.42,7168.16 4077.27,7168.56 4078.11,7168.88 4078.94,7169.13 4079.76,7169.3 4080.57,7169.41 4081.38,7169.46 4082.18,7169.45 4082.99,7169.4 4084.22,7169.25 4085.89,7168.92 4091.38,7167.57 4093.99,7167.04 4096.26,7166.73 4098.09,7166.58 4100.03,7166.53 4102.1,7166.6 4066.6,7202.1 4066.53,7200.03 4066.58,7198.09 4066.73,7196.26 4067.04,7193.99 4067.57,7191.38 4068.92,7185.89 4069.25,7184.22 4069.4,7182.99 4069.45,7182.18 4069.46,7181.38 4069.41,7180.57 4069.3,7179.76 4069.13,7178.94 4068.88,7178.11 4068.56,7177.27 4068.16,7176.42 4067.67,7175.55 4067.09,7174.66 4066.41,7173.74 4065.63,7172.79
  region net ~INT: 4071.32,7235.75 4064.25,7228.68 4065.63,7227.21 4066.41,7226.26 4067.09,7225.34 4067.67,7224.45 4068.16,7223.58 4068.56,7222.73 4068.88,7221.89 4069.13,7221.06 4069.3,7220.24 4069.41,7219.43 4069.46,7218.62 4069.45,7217.82 4069.4,7217.01 4069.25,7215.78 4068.92,7214.11 4067.57,7208.62 4067.04,7206.01 4066.73,7203.74 4066.58,7201.91 4066.53,7199.97 4066.6,7197.9 4102.1,7233.4 4100.03,7233.47 4098.09,7233.42 4096.26,7233.27 4093.99,7232.96 4091.38,7232.43 4085.89,7231.08 4084.22,7230.75 4082.99,7230.6 4082.18,7230.55 4081.38,7230.54 4080.57,7230.59 4079.76,7230.7 4078.94,7230.87 4078.11,7231.12 4077.27,7231.44 4076.42,7231.84 4075.55,7232.33 4074.66,7232.91 4073.74,7233.59 4072.79,7234.37
  region net SCK: 5195,5854.44 5205,5854.44 5205.07,5856.46 5205.18,5857.68 5205.35,5858.81 5205.57,5859.85 5205.84,5860.81 5206.16,5861.7 5206.53,5862.52 5206.94,5863.28 5207.39,5863.98 5207.89,5864.63 5208.43,5865.24 5209,5865.8 5209.61,5866.34 5210.59,5867.1 5212,5868.05 5216.84,5870.97 5219.06,5872.45 5220.89,5873.83 5222.28,5875.02 5223.69,5876.36 5225.1,5877.87 5174.9,5877.87 5176.31,5876.36 5177.72,5875.02 5179.11,5873.83 5180.94,5872.45 5183.16,5870.97 5188,5868.05 5189.41,5867.1 5190.39,5866.34 5191,5865.8 5191.57,5865.24 5192.11,5864.63 5192.61,5863.98 5193.06,5863.28 5193.47,5862.52 5193.84,5861.7 5194.16,5860.81 5194.43,5859.85 5194.65,5858.81 5194.82,5857.68 5194.93,5856.46
  region net A2: 6170,6758.66 6180,6758.66 6180.02,6759.23 6180.09,6759.8 6180.2,6760.37 6180.34,6760.93 6180.52,6761.49 6180.98,6762.6 6181.54,6763.68 6182.19,6764.72 6182.89,6765.7 6184,6767.06 6166,6767.06 6167.11,6765.7 6167.81,6764.72 6168.46,6763.68 6169.02,6762.6 6169.48,6761.49 6169.66,6760.93 6169.8,6760.37 6169.91,6759.8 6169.98,6759.23
  region net A2: 6620,6483.66 6630,6483.66 6630.02,6484.23 6630.09,6484.8 6630.2,6485.37 6630.34,6485.93 6630.52,6486.49 6630.98,6487.6 6631.54,6488.68 6632.19,6489.72 6632.89,6490.7 6634,6492.06 6616,6492.06 6617.11,6490.7 6617.81,6489.72 6618.46,6488.68 6619.02,6487.6 6619.48,6486.49 6619.66,6485.93 6619.8,6485.37 6619.91,6484.8 6619.98,6484.23
  region net ~INT: 5683.66,4080 5683.66,4070 5684.23,4069.98 5684.8,4069.91 5685.37,4069.8 5685.93,4069.66 5686.49,4069.48 5687.6,4069.02 5688.68,4068.46 5689.72,4067.81 5690.7,4067.11 5692.06,4066 5692.06,4084 5690.7,4082.89 5689.72,4082.19 5688.68,4081.54 5687.6,4080.98 5686.49,4080.52 5685.93,4080.34 5685.37,4080.2 5684.8,4080.09 5684.23,4080.02
  region net ~INT: 5716.34,4070 5716.34,4080 5715.77,4080.02 5715.2,4080.09 5714.63,4080.2 5714.07,4080.34 5713.51,4080.52 5712.4,4080.98 5711.32,4081.54 5710.28,4082.19 5709.3,4082.89 5707.94,4084 5707.94,4066 5709.3,4067.11 5710.28,4067.81 5711.32,4068.46 5712.4,4069.02 5713.51,4069.48 5714.07,4069.66 5714.63,4069.8 5715.2,4069.91 5715.77,4069.98
  region net ~INT: 5705,5191.34 5695,5191.34 5694.98,5190.77 5694.91,5190.2 5694.8,5189.63 5694.66,5189.07 5694.48,5188.51 5694.02,5187.4 5693.46,5186.32 5692.81,5185.28 5692.11,5184.3 5691,5182.94 5709,5182.94 5707.89,5184.3 5707.19,5185.28 5706.54,5186.32 5705.98,5187.4 5705.52,5188.51 5705.34,5189.07 5705.2,5189.63 5705.09,5190.2 5705.02,5190.77

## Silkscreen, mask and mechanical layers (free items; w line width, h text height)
Top Silkscreen Layer:
  lines w6 net "": 4252,7225 4312,7225 ; 4476,7384 4476,7444 ; 4675,4277 4675,4354 ; 5176,7384 5176,7444 ; 5876,7384 5876,7444 ; 6575,4277 6575,4337 ; 6576,7384 6576,7444 ; 7276,7384 7276,7444 ; 7475,4277 7475,4337 ; 7684,6624 7744,6624 ; 7759,7274 7819,7274
  text "VCC" at 4172.49,7556.32 h29.38
  text "VCC" at 4793.68,7455.23 h29.38 r90
  text "VCC" at 5493.68,7455.23 h29.38 r90
  text "VCC" at 6193.68,7455.23 h29.38 r90
  text "VCC" at 6893.68,7455.23 h29.38 r90
  text "VCC" at 7593.68,7455.23 h29.38 r90
  text "GND" at 4393.68,7451.52 h29.38 r90
  text "INT" at 4493.68,7451.52 h29.38 r90
  text "SCL" at 4593.68,7451.52 h29.38 r90
  text "SDA" at 4693.68,7451.52 h29.38 r90
  text "GND" at 5093.68,7451.52 h29.38 r90
  text "INT" at 5193.68,7451.52 h29.38 r90
  text "SCL" at 5293.68,7451.52 h29.38 r90
  text "SDA" at 5393.68,7451.52 h29.38 r90
  text "GND" at 5793.68,7451.52 h29.38 r90
  text "INT" at 5893.68,7451.52 h29.38 r90
  text "SCL" at 5993.68,7451.52 h29.38 r90
  text "SDA" at 6093.68,7451.52 h29.38 r90
  text "GND" at 6493.68,7451.52 h29.38 r90
  text "INT" at 6593.68,7451.52 h29.38 r90
  text "SCL" at 6693.68,7451.52 h29.38 r90
  text "SDA" at 6793.68,7451.52 h29.38 r90
  text "GND" at 7193.68,7451.52 h29.38 r90
  text "INT" at 7293.68,7451.52 h29.38 r90
  text "SCL" at 7393.68,7451.52 h29.38 r90
  text "SDA" at 7493.68,7451.52 h29.38 r90
  text "SDA" at 4247.49,7406.32 h29.38
  text "SCL" at 4247.49,7306.32 h29.38
  text "GND" at 7830.23,7306.32 h29.38
  text "INT" at 7826.52,7256.32 h29.38
  text "INT" at 4247.49,7206.32 h29.38
  text "GND" at 4172.49,7106.32 h29.38
  text "SCL" at 7751.52,7106.32 h29.38
  text "SDA" at 7751.52,7006.32 h29.38
  text "VCC" at 7755.23,6906.32 h29.38
  text "GND" at 7751.52,6706.32 h29.38
  text "INT" at 7751.52,6606.32 h29.38
  text "1" at 6202.79,6581.35 h29.6
  text "1" at 6611.6,6581.35 h29.6
  text "SCL" at 7751.52,6506.32 h29.38
  text "0" at 6202.79,6431.35 h29.6
  text "0" at 6611.6,6431.35 h29.6
  text "SDA" at 7751.52,6406.32 h29.38
  text "VCC" at 7755.23,6306.32 h29.38
  text "AC-" at 7623.33,6006.32 h29.38
  text "COPI" at 5093.68,5831.52 h29.38 r90
  text "D7" at 5593.68,5828.94 h29.38 r90
  text "CIPO" at 4993.68,5827.82 h29.38 r90
  text "GND" at 4793.68,5826.52 h29.38 r90
  text "VCC" at 4893.68,5826.52 h29.38 r90
  text "SCK" at 5193.68,5826.52 h29.38 r90
  text "~D9" at 5393.68,5826.52 h29.38 r90
  text "CS" at 5293.68,5825.23 h29.38 r90
  text "D8" at 5493.68,5825.23 h29.38 r90
  text "AC+" at 7630.23,5806.32 h29.38
  text "VCC" at 7671.53,5506.32 h29.38
  text "GND" at 7680.23,5406.32 h29.38
  text "CLK" at 7830.23,5306.32 h29.38
  text "DAT" at 7830.23,5206.32 h29.38
  text "VINCENT ALFRED B. TOMAS" at 5772.47,5193.65 h54.52
  text "DESIGN BY" at 5008.25,5193.01 h54.52
  text "ArgonArc" at 5027.27,5174.36 h420
  text "RST" at 7830.23,5106.32 h29.38
  text "IN COLLABORATION WITH:" at 4887.4,4963.98 h40.88
  text "INSTRUCTOR:" at 6057.15,4963.98 h40.88
  text "GND" at 7826.52,4906.32 h29.38
  text "WRENN HARVYL F. TAJANTAJAN" at 4880.22,4863.98 h40.88
  text "ENGR. VINCE JEBRYL G. MONTERO, ECE" at 6015.86,4863.98 h40.88
  text "GND" at 7826.52,4806.32 h29.38
  text "DALE ANTHONY A. HEMPLO" at 4887.4,4788.98 h40.88
  text "WOODZER L. PLAZA" at 4898.17,4713.98 h40.88
  text "OUT" at 7826.52,4706.32 h29.38
  text "VCC" at 7830.23,4606.32 h29.38
  text "HTTPS://GITHUB.COM/VATOMAS/POWERTRACK" at 4860.47,4588.98 h40.88
  text "VERSION 65ED6F54" at 4905.72,4535.05 h29.38
  text "JLCJLCJLCJLC" at 5435.88,4535.05 h29.38
  text "A3" at 7093.68,4273.78 h29.38 r90
  text "A2" at 7193.68,4273.78 h29.38 r90
  text "A1" at 7293.68,4273.78 h29.38 r90
  text "SCL" at 4093.68,4272.49 h29.38 r90
  text "SDA" at 4193.68,4272.49 h29.38 r90
  text "VCC" at 4293.68,4272.49 h29.38 r90
  text "GND" at 4393.68,4272.49 h29.38 r90
  text "GND" at 4593.68,4272.49 h29.38 r90
  text "RST" at 4693.68,4272.49 h29.38 r90
  text "GND" at 6493.68,4272.49 h29.38 r90
  text "INT" at 6593.68,4272.49 h29.38 r90
  text "SCL" at 6693.68,4272.49 h29.38 r90
  text "SDA" at 6793.68,4272.49 h29.38 r90
  text "VCC" at 6893.68,4272.49 h29.38 r90
  text "INT" at 7493.68,4272.49 h29.38 r90
  text "GND" at 7593.68,4272.49 h29.38 r90
  text "ANALOG" at 7037,4075 h50
Mechanical Layer:
  circle w1 net "": c7900,4200 r62.99
  circle w1 net "": c4100,7700 r62.99
  circle w1 net "": c7900,7700 r62.99
Mech6:
  lines w10 net "": 8400,6550 8400,7250 10300,7250 10300,4050 9599.99,4050 9600.51,6550 8400,6550
Mech15:
  circle w10 net "": c7900,4200 r110.24
  circle w10 net "": c4100,7700 r110.24
  circle w10 net "": c7900,7700 r110.24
